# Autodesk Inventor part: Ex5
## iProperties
Author: Administrator
Created: 2001-01
Part Number: Ex5
Document SubType Name: Modeling
Designer: Administrator
Control State: 0
Master: False
Checked Out: False
PropertySet Name: Design Tracking Control
Shininess: 0.0
PropertySet Name: _Private Model Information
Density: 0.0
Volumn: 0.0
Area: 0.0
PropertySet Name: Model Information
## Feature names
1. Extrusion1
2. Hole1
3. Rectangular Pattern1
4. Sweep1
5. circle_plate [Extrusion]
6. slot_circle [Extrusion]
7. Circular Pattern1
